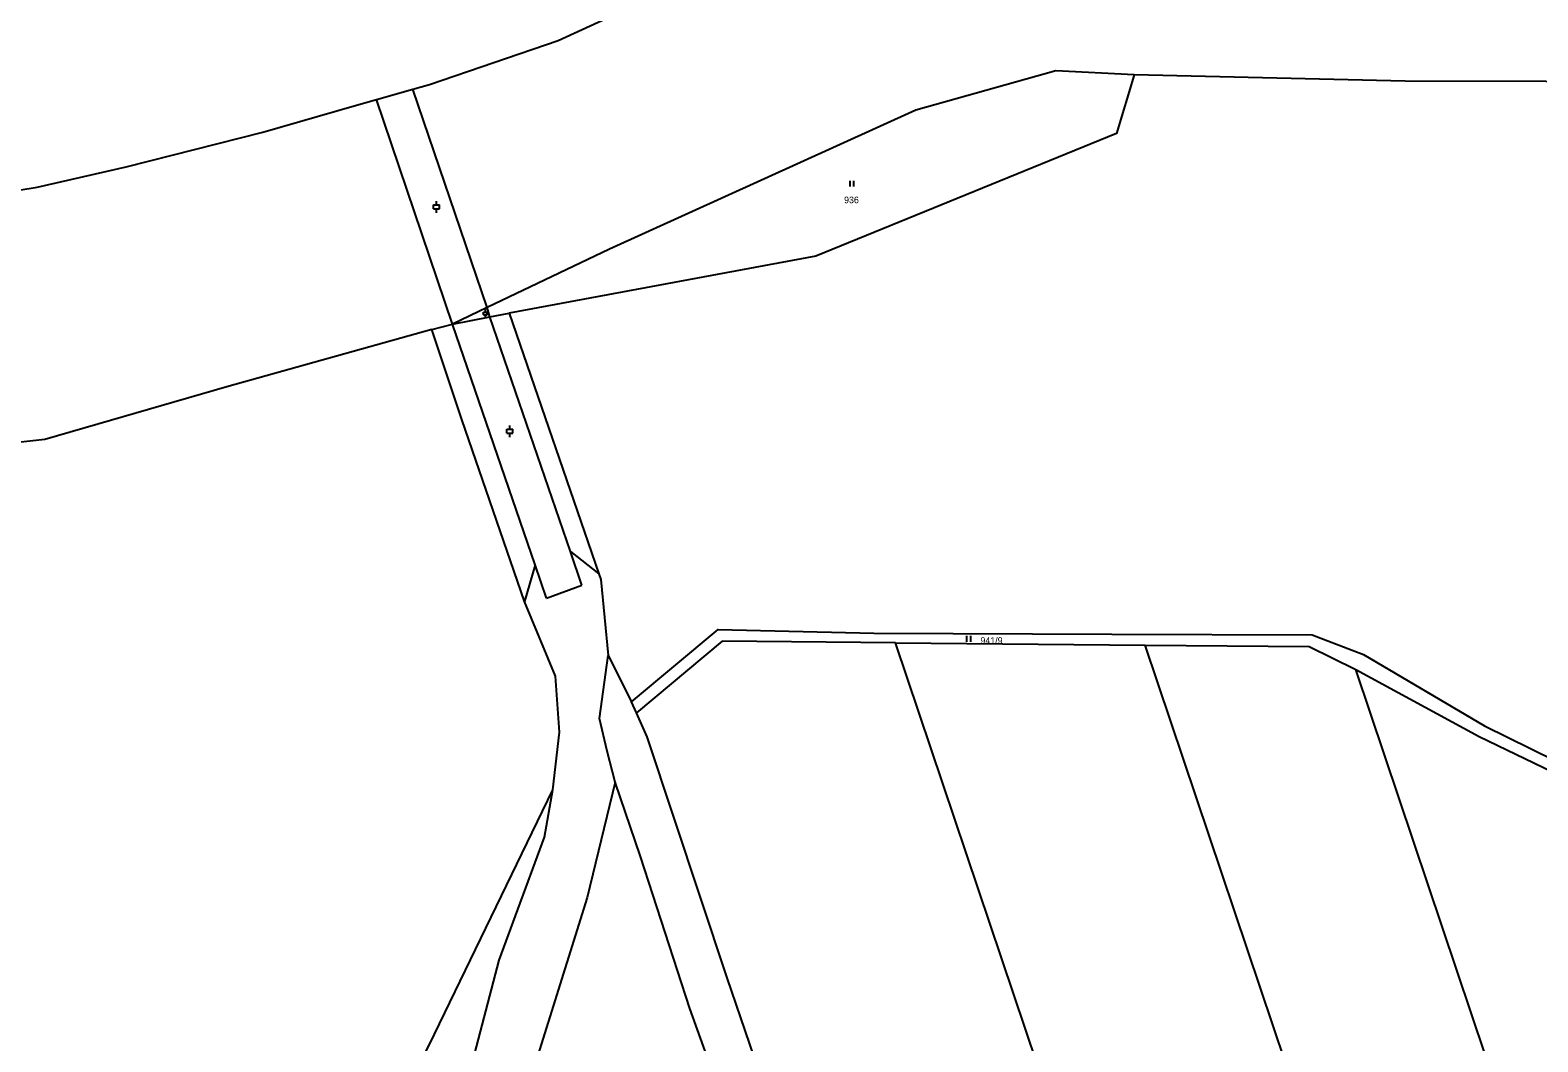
# Model space of a CAD drawing. Extents: x -7483133 to -743169, y -11317770 to -1127091.
# Drawn here: x -750645.6 to -750258.6, y -1130967.2 to -1130707.4 of the extents above; entities that cross this region are included whole.
import ezdxf

# ---------------------------------------------------------------- set-up
doc = ezdxf.new("R2010")
doc.units = 0
for name, color, linetype in [('Hranice parcel', 7, 'Continuous'), ('Parcelní čísla', 7, 'Continuous'), ('Vnitřní kresba', 7, 'Continuous'), ('Značky kultur', 7, 'Continuous')]:
    doc.layers.add(name, color=color, linetype=linetype)

msp = doc.modelspace()

# ---------------------------------------------------------------- linework, layer by layer
at = {"layer": 'Hranice parcel'}
for p, q in [((-750542.51, -1130784.25), (-750537.23, -1130782.88)), ((-750423.45, -1130864.72), (-750359.42, -1130865.31)), ((-750497.26, -1130867.97), (-750491.25, -1130879.86)), ((-750489.98, -1130882.7), (-750491.25, -1130879.86))]:
    msp.add_line(p, q, dxfattribs=at)
for points in [[(-749828.37, -1130639.41), (-749915.33, -1130715.71), (-750029.45, -1130718.38), (-750148.19, -1130720.88), (-750292.64, -1130720.5), (-750362.26, -1130718.85)], [(-750543.14, -1130721.36), (-750510.08, -1130710.04), (-750480.18, -1130696.3), (-750425.99, -1130664.25), (-750395.01, -1130654.25)], [(-750362.26, -1130718.85), (-750382.37, -1130717.85), (-750418.27, -1130727.96), (-750496.94, -1130763.69), (-750528.35, -1130778.65), (-750537.23, -1130782.88)], [(-750562.47, -1130726.85), (-750556.71, -1130725.21), (-750547.39, -1130722.57), (-750543.14, -1130721.36)], [(-750362.26, -1130718.85), (-750366.74, -1130733.92), (-750443.97, -1130765.43), (-750522.68, -1130780.11)], [(-750677.41, -1130753.17), (-750669.01, -1130751.86), (-750643.79, -1130747.71), (-750620.98, -1130742.49), (-750585.9, -1130733.64), (-750562.47, -1130726.85)], [(-750537.23, -1130782.88), (-750527.59, -1130781.02), (-750522.68, -1130780.11)], [(-750522.68, -1130780.11), (-750499.63, -1130847.01), (-750499.12, -1130848.49), (-750497.26, -1130867.97)], [(-750542.51, -1130784.25), (-750595.13, -1130799), (-750641.84, -1130812.5), (-750706.94, -1130819.8)], [(-750511.43, -1130902.47), (-750509.76, -1130887.71), (-750510.81, -1130873.25), (-750518.73, -1130854.13), (-750534.78, -1130807.35), (-750542.51, -1130784.25)], [(-750491.25, -1130879.86), (-750469.04, -1130861.3), (-750429.04, -1130862.24), (-750367.95, -1130862.53), (-750316.54, -1130862.71), (-750303.39, -1130867.71), (-750272.3, -1130886.08), (-750242.29, -1130900.85), (-750215.89, -1130913.25), (-750197.91, -1130920.02), (-750183.56, -1130928.08)], [(-750423.45, -1130864.72), (-750467.96, -1130864.31), (-750489.98, -1130882.7)], [(-750332.51, -1131135.35), (-750377.98, -1131000.04), (-750423.45, -1130864.72)], [(-750495.43, -1130900.48), (-750497.49, -1130892.54), (-750499.47, -1130884.13), (-750497.26, -1130867.97)], [(-750359.42, -1130865.31), (-750317.3, -1130865.7), (-750305.36, -1130871.62)], [(-750274.04, -1131119.43), (-750316.73, -1130992.37), (-750359.42, -1130865.31)], [(-750305.36, -1130871.62), (-750273.65, -1130888.76), (-750217.17, -1130915.97), (-750205.4, -1130921.38)], [(-750223.88, -1131114.14), (-750264.62, -1130992.88), (-750305.36, -1130871.62)], [(-750383.69, -1131147.48), (-750402.83, -1131122.9), (-750410.73, -1131109.04), (-750424.07, -1131076.84), (-750442.36, -1131021.87), (-750466.73, -1130950.73), (-750487.24, -1130888.84), (-750489.98, -1130882.7)], [(-750579.43, -1131041.4), (-750541.82, -1130965.24), (-750511.43, -1130902.47)], [(-750547.16, -1131015.06), (-750541.48, -1131002.77), (-750533.47, -1130977.66), (-750525.19, -1130946.2), (-750513.6, -1130914.64), (-750511.43, -1130902.47)], [(-750495.43, -1130900.48), (-750502.66, -1130930.1), (-750517.9, -1130978.8), (-750528.5, -1131007.43), (-750533.48, -1131028.12)], [(-750446.13, -1131110.72), (-750443.13, -1131090.87), (-750443.7, -1131068.64), (-750447.41, -1131045.86), (-750453.97, -1131020.75), (-750476.26, -1130958.59), (-750488.96, -1130919.57), (-750495.43, -1130900.48)]]:
    msp.add_lwpolyline(points, dxfattribs=at)
at = {"layer": 'Vnitřní kresba'}
for p, q in [((-750537.23, -1130782.88), (-750556.71, -1130725.21)), ((-750528.35, -1130778.65), (-750547.39, -1130722.57)), ((-750527.59, -1130781.02), (-750528.35, -1130778.65)), ((-750516.01, -1130844.71), (-750537.23, -1130782.88)), ((-750506.94, -1130841.29), (-750527.59, -1130781.02)), ((-750506.94, -1130841.29), (-750499.63, -1130847.01)), ((-750503.98, -1130849.93), (-750506.94, -1130841.29)), ((-750516.01, -1130844.71), (-750518.73, -1130854.13)), ((-750513.09, -1130853.23), (-750516.01, -1130844.71)), ((-750513.09, -1130853.23), (-750503.98, -1130849.93))]:
    msp.add_line(p, q, dxfattribs=at)
at = {"layer": 'Značky kultur'}
for p, q in [((-750435.15, -1130747.58), (-750435.15, -1130746.08)), ((-750434.15, -1130747.58), (-750434.15, -1130746.08)), ((-750542.05, -1130752.29), (-750540.55, -1130752.29)), ((-750542.05, -1130753.29), (-750542.05, -1130752.29)), ((-750541.3, -1130752.29), (-750541.3, -1130751.29)), ((-750540.55, -1130753.29), (-750540.55, -1130752.29)), ((-750542.05, -1130753.29), (-750540.55, -1130753.29)), ((-750541.3, -1130754.29), (-750541.3, -1130753.29)), ((-750529.27, -1130779.83), (-750528.27, -1130779.83)), ((-750529.27, -1130780.5), (-750529.27, -1130779.83)), ((-750528.77, -1130779.83), (-750528.77, -1130779.16)), ((-750528.27, -1130780.5), (-750528.27, -1130779.83)), ((-750529.27, -1130780.5), (-750528.27, -1130780.5)), ((-750528.77, -1130781.17), (-750528.77, -1130780.5)), ((-750523.26, -1130809.89), (-750521.76, -1130809.89)), ((-750523.26, -1130810.89), (-750523.26, -1130809.89)), ((-750522.51, -1130809.89), (-750522.51, -1130808.89)), ((-750521.76, -1130810.89), (-750521.76, -1130809.89)), ((-750523.26, -1130810.89), (-750521.76, -1130810.89)), ((-750522.51, -1130811.89), (-750522.51, -1130810.89)), ((-750405.19, -1130864.45), (-750405.19, -1130862.95)), ((-750404.19, -1130864.45), (-750404.19, -1130862.95))]:
    msp.add_line(p, q, dxfattribs=at)

# ---------------------------------------------------------------- texts
at = {"layer": 'Parcelní čísla'}
for s, p in [('936', (-750436.69, -1130751.86)), ('941/9', (-750401.69, -1130864.99))]:
    msp.add_text(s, height=1.7, dxfattribs=at).set_placement(p)

doc.saveas('drawing.dxf')
